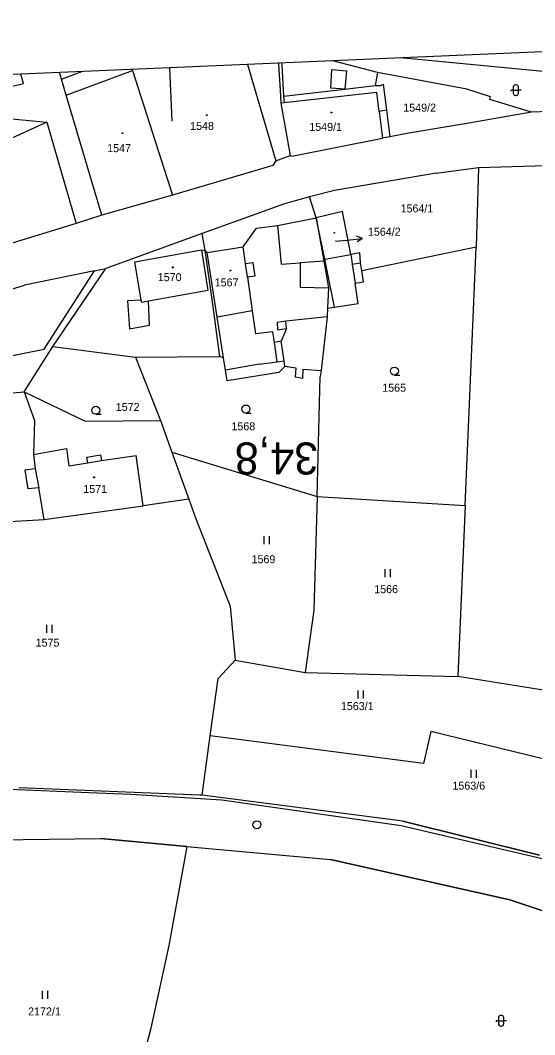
# Model space of a CAD drawing. Extents: x -806456 to -805395, y -1150847 to -1150506.
# Drawn here: x -805645 to -805548.5, y -1150696.2 to -1150506.1 of the extents above; entities that cross this region are included whole.
import ezdxf

# ---------------------------------------------------------------- set-up
doc = ezdxf.new("R2010")
doc.units = 0
for name, color, linetype in [('Default', 7, 'Continuous'), ('formát', 7, 'Continuous'), ('kilometráž - vrstava 7', 7, 'Continuous'), ('kn_celek - Cisla parcel pomocna', 7, 'Continuous'), ('kn_celek - Cisla pozemkovych parcel', 7, 'Continuous'), ('kn_celek - Cisla stavebnich parcel', 7, 'Continuous'), ('kn_celek - Hranice parcel', 7, 'Continuous'), ('kn_celek - Vnitrni kresby', 7, 'Continuous'), ('kn_celek - Znacky budov', 7, 'Continuous'), ('kn_celek - Znacky kultur', 7, 'Continuous'), ('plochy - SZDC', 7, 'Continuous'), ('PSR_C2_2_trasa_Vimperk - Kabelová trasa', 7, 'Continuous')]:
    doc.layers.add(name, color=color, linetype=linetype)

# ---------------------------------------------------------------- blocks, each defined once
blk = doc.blocks.new('316')
at = {"layer": 'Default'}
for p, q in [((0.5, 20), (-0.5, 20)), ((-8.3, 10), (-10, 8.1)), ((-5, 10), (-8.3, 10)), ((-5, 15.5), (-5, 4.5)), ((-5, 10), (5, 10)), ((-0.5, 0), (0.5, 0)), ((5, 4.5), (5, 15.5)), ((10, 10), (5, 10))]:
    blk.add_line(p, q, dxfattribs=at)
for centre, start, end in [((-0.5, 15.5), 90, 180), ((0.5, 15.5), 0, 90), ((-0.5, 4.5), 180, 270), ((0.5, 4.5), 270, 0)]:
    blk.add_arc(centre, 4.5, start, end, dxfattribs=at)
blk = doc.blocks.new('304')
at = {"layer": 'Default'}
blk.add_line((-0.1, 0), (9.9, 0), dxfattribs=at)
blk.add_circle((-0.1, 7.5), 7.5, dxfattribs=at)
blk = doc.blocks.new('306')
at = {"layer": 'Default'}
for p, q in [((-5.2, 0), (-5.2, 15)), ((4.8, 0), (4.8, 15))]:
    blk.add_line(p, q, dxfattribs=at)
blk = doc.blocks.new('402')
at = {"layer": 'Default'}
for p, q in [((-0.8, 0.8), (0.7, 0.8)), ((-0.8, 0.8), (-0.8, -0.7)), ((0.7, 0.8), (0.7, -0.7)), ((0.7, -0.7), (-0.8, -0.7))]:
    blk.add_line(p, q, dxfattribs=at)
blk = doc.blocks.new('Z61')
at = {"layer": 'Default'}
for p, q in [((0, 0), (30, 0)), ((30, 0), (19.2, 5.3)), ((30, 0), (19.2, -5.3))]:
    blk.add_line(p, q, dxfattribs=at)

msp = doc.modelspace()

# ---------------------------------------------------------------- linework, layer by layer
at = {"layer": 'formát'}
for p, q in [((-805407.21, -1150506.06), (-805617.02, -1150514.97)), ((-805617.02, -1150514.97), (-805826.83, -1150523.88)), ((-805617.02, -1150514.97), (-805616.59, -1150524.96))]:
    msp.add_line(p, q, dxfattribs=at)
at = {"layer": 'kilometráž - vrstava 7'}
msp.add_circle((-805600.62, -1150656.85), 0.75, dxfattribs=at)
at = {"layer": 'kn_celek - Cisla parcel pomocna'}
msp.add_line((-805585.87, -1150547.48), (-805583.79, -1150547.26), dxfattribs=at)
at = {"layer": 'kn_celek - Hranice parcel'}
for p, q in [((-805545.02, -1150515.82), (-805573.69, -1150513.13)), ((-805596.63, -1150514.1), (-805596.55, -1150514.37)), ((-805596.57, -1150514.1), (-805596.55, -1150514.37)), ((-805596.55, -1150514.37), (-805596.25, -1150519.18)), ((-805577.98, -1150515.83), (-805586.36, -1150513.67)), ((-805623.92, -1150515.45), (-805623.97, -1150515.26)), ((-805623.92, -1150515.45), (-805616.46, -1150538.83)), ((-805577.98, -1150515.83), (-805578.46, -1150518.31)), ((-805561.26, -1150518.96), (-805577.98, -1150515.83)), ((-805578.46, -1150518.31), (-805577.47, -1150518.27)), ((-805577.47, -1150518.27), (-805576.96, -1150518.06)), ((-805576.96, -1150518.06), (-805576.3, -1150522.94)), ((-805556.85, -1150520.42), (-805561.26, -1150518.96)), ((-805596.25, -1150519.18), (-805596.13, -1150521.6)), ((-805556.98, -1150520.91), (-805556.85, -1150520.42)), ((-805596.13, -1150521.6), (-805594.41, -1150531.4)), ((-805549.13, -1150523.27), (-805556.98, -1150520.91)), ((-805511.56, -1150521.75), (-805549.13, -1150523.27)), ((-805659.38, -1150523.36), (-805639.97, -1150525.18)), ((-805576.3, -1150522.94), (-805575.71, -1150527.92)), ((-805549.13, -1150523.27), (-805560.9, -1150525.36)), ((-805639.97, -1150525.18), (-805634.52, -1150544.15)), ((-805560.9, -1150525.36), (-805572.16, -1150527.23)), ((-805594.09, -1150531.56), (-805577.06, -1150528.18)), ((-805575.71, -1150527.92), (-805577.06, -1150528.18)), ((-805572.16, -1150527.23), (-805575.71, -1150527.92)), ((-805597.08, -1150532.42), (-805594.41, -1150531.4)), ((-805594.41, -1150531.4), (-805594.09, -1150531.56)), ((-805597.62, -1150533.3), (-805616.46, -1150538.83)), ((-805597.08, -1150532.42), (-805597.62, -1150533.3)), ((-805567, -1150534.69), (-805559.08, -1150533.65)), ((-805559.08, -1150533.65), (-805559.52, -1150548.6)), ((-805559.08, -1150533.65), (-805552.74, -1150533.48)), ((-805552.74, -1150533.48), (-805531.55, -1150532.9)), ((-805567, -1150534.69), (-805586.09, -1150537.99)), ((-805586.09, -1150537.99), (-805590.75, -1150539.15)), ((-805616.46, -1150538.83), (-805629.68, -1150542.61)), ((-805590.75, -1150539.15), (-805595.46, -1150540.47)), ((-805589.49, -1150543.12), (-805590.75, -1150539.15)), ((-805595.46, -1150540.47), (-805610.86, -1150546.01)), ((-805629.68, -1150542.61), (-805634.52, -1150544.15)), ((-805584.56, -1150541.93), (-805589.49, -1150543.12)), ((-805589.49, -1150543.12), (-805588.08, -1150551.24)), ((-805583.02, -1150549.97), (-805584.56, -1150541.93)), ((-805634.52, -1150544.15), (-805647.9, -1150548.27)), ((-805610.86, -1150546.01), (-805628.96, -1150552.57)), ((-805610.34, -1150549.2), (-805610.86, -1150546.01)), ((-805608.95, -1150558.85), (-805610.34, -1150549.2)), ((-805559.52, -1150548.6), (-805580.96, -1150553)), ((-805561.59, -1150597.03), (-805559.52, -1150548.6)), ((-805588.08, -1150551.24), (-805587.21, -1150556.23)), ((-805581.35, -1150549.67), (-805583.02, -1150549.97)), ((-805581.2, -1150551.5), (-805581.35, -1150549.67)), ((-805631.08, -1150553.04), (-805644.16, -1150555.7)), ((-805640.5, -1150567.71), (-805631.08, -1150553.04)), ((-805638.87, -1150567.2), (-805628.96, -1150552.57)), ((-805631.08, -1150553.04), (-805628.96, -1150552.57)), ((-805580.96, -1150553), (-805581.2, -1150551.5)), ((-805580.65, -1150555.07), (-805580.96, -1150553)), ((-805582.2, -1150555.31), (-805580.65, -1150555.07)), ((-805683.25, -1150567.84), (-805644.16, -1150555.7)), ((-805587.21, -1150556.23), (-805587.39, -1150560.01)), ((-805581.62, -1150559.15), (-805582.2, -1150555.31)), ((-805607.59, -1150569.08), (-805608.95, -1150558.85)), ((-805587.39, -1150560.01), (-805587.46, -1150561.66)), ((-805587.39, -1150560.01), (-805586.06, -1150559.81)), ((-805586.06, -1150559.81), (-805581.62, -1150559.15)), ((-805587.46, -1150561.66), (-805588.6, -1150571.69)), ((-805657.32, -1150571.01), (-805640.5, -1150567.71)), ((-805644.23, -1150575.69), (-805638.87, -1150567.2)), ((-805638.87, -1150567.2), (-805623.37, -1150569.23)), ((-805623.37, -1150569.23), (-805607.59, -1150569.08)), ((-805623.37, -1150569.23), (-805618.69, -1150581.09)), ((-805606.9, -1150569.31), (-805607.59, -1150569.08)), ((-805606.51, -1150571.62), (-805606.9, -1150569.31)), ((-805606.2, -1150573.64), (-805606.51, -1150571.62)), ((-805596.52, -1150572.06), (-805606.2, -1150573.64)), ((-805595.38, -1150570.95), (-805596.52, -1150572.06)), ((-805593.25, -1150571.25), (-805595.38, -1150570.95)), ((-805593.39, -1150572.95), (-805593.25, -1150571.25)), ((-805591.98, -1150571.46), (-805592.07, -1150573.19)), ((-805591.98, -1150571.46), (-805588.6, -1150571.69)), ((-805588.6, -1150571.69), (-805588.73, -1150572.86)), ((-805592.07, -1150573.19), (-805593.39, -1150572.95)), ((-805589.35, -1150595.34), (-805588.73, -1150572.86)), ((-805687.22, -1150579.45), (-805644.23, -1150575.69)), ((-805644.23, -1150575.69), (-805642.33, -1150581.09)), ((-805644.23, -1150575.69), (-805632.79, -1150581.21)), ((-805642.33, -1150581.09), (-805642.49, -1150587.43)), ((-805632.79, -1150581.21), (-805618.69, -1150581.09)), ((-805618.69, -1150581.09), (-805616.57, -1150587)), ((-805642.49, -1150587.43), (-805642.17, -1150590.12)), ((-805616.57, -1150587), (-805589.35, -1150595.34)), ((-805616.57, -1150587), (-805613.4, -1150595.85)), ((-805642.17, -1150590.12), (-805644.14, -1150590.41)), ((-805644.14, -1150590.41), (-805643.57, -1150593.9)), ((-805641.47, -1150593.73), (-805643.57, -1150593.9)), ((-805640.51, -1150599.62), (-805641.47, -1150593.73)), ((-805613.4, -1150595.85), (-805621.95, -1150597.06)), ((-805613.4, -1150595.85), (-805612.11, -1150599.32)), ((-805589.35, -1150595.34), (-805589.93, -1150616.61)), ((-805589.35, -1150595.34), (-805561.59, -1150597.03)), ((-805640.51, -1150599.62), (-805621.95, -1150597.06)), ((-805561.59, -1150597.03), (-805562.96, -1150629.07)), ((-805680.36, -1150601.92), (-805640.51, -1150599.62)), ((-805612.11, -1150599.32), (-805605.63, -1150615.87)), ((-805605.63, -1150615.87), (-805604.67, -1150626.03)), ((-805589.93, -1150616.61), (-805591.55, -1150628.29)), ((-805604.67, -1150626.03), (-805607.89, -1150629.47)), ((-805604.67, -1150626.03), (-805591.55, -1150628.29)), ((-805591.55, -1150628.29), (-805562.96, -1150629.07)), ((-805541.61, -1150632.52), (-805562.96, -1150629.07)), ((-805609.35, -1150640.16), (-805607.89, -1150629.47)), ((-805610.86, -1150651.29), (-805609.35, -1150640.16)), ((-805569.41, -1150645.37), (-805609.35, -1150640.16)), ((-805568.04, -1150639.35), (-805569.41, -1150645.37)), ((-805542.66, -1150645.56), (-805568.04, -1150639.35)), ((-805611.34, -1150651.29), (-805645.21, -1150649.93)), ((-805610.86, -1150651.29), (-805611.34, -1150651.29)), ((-805573.24, -1150656.2), (-805610.86, -1150651.29)), ((-805573.24, -1150656.2), (-805547.66, -1150662.54)), ((-805660.75, -1150659.79), (-805629.87, -1150659.45)), ((-805613.77, -1150660.92), (-805629.87, -1150659.45)), ((-805613.77, -1150660.92), (-805614.34, -1150664.04)), ((-805613.77, -1150660.92), (-805586.79, -1150663.39)), ((-805553.22, -1150670.95), (-805586.79, -1150663.39)), ((-805614.34, -1150664.04), (-805617.15, -1150679.49)), ((-805525.6, -1150680.1), (-805553.22, -1150670.95)), ((-805617.15, -1150679.49), (-805620.5, -1150694.98)), ((-805620.5, -1150694.98), (-805625.71, -1150715.25))]:
    msp.add_line(p, q, dxfattribs=at)
at = {"layer": 'kn_celek - Vnitrni kresby'}
for p, q in [((-805602.39, -1150514.35), (-805597.08, -1150532.42)), ((-805596, -1150514.08), (-805595.96, -1150514.45)), ((-805595.96, -1150514.45), (-805595.61, -1150520.29)), ((-805644.38, -1150517.91), (-805644.86, -1150516.15)), ((-805637.24, -1150517.09), (-805637.61, -1150515.84)), ((-805637.24, -1150517.09), (-805633.45, -1150515.67)), ((-805636.35, -1150520.07), (-805623.92, -1150515.45)), ((-805586.78, -1150518.78), (-805586.57, -1150515.31)), ((-805586.57, -1150515.31), (-805583.83, -1150515.54)), ((-805583.83, -1150515.54), (-805584.13, -1150518.98)), ((-805653.92, -1150520.23), (-805644.38, -1150517.91)), ((-805636.35, -1150520.07), (-805637.24, -1150517.09)), ((-805584.13, -1150518.98), (-805586.78, -1150518.78)), ((-805584.13, -1150518.98), (-805578.46, -1150518.31)), ((-805629.68, -1150542.61), (-805636.35, -1150520.07)), ((-805595.61, -1150520.29), (-805584.13, -1150518.98)), ((-805595.61, -1150520.29), (-805595.53, -1150521.53)), ((-805578.16, -1150519.57), (-805595.53, -1150521.53)), ((-805577.7, -1150523.19), (-805578.16, -1150519.57)), ((-805595.53, -1150521.53), (-805596.13, -1150521.6)), ((-805576.3, -1150522.94), (-805577.7, -1150523.19)), ((-805577.7, -1150523.19), (-805577.06, -1150528.18)), ((-805639.97, -1150525.18), (-805648.16, -1150528.9)), ((-805596.77, -1150544.52), (-805589.49, -1150543.12)), ((-805587.9, -1150550.85), (-805589.49, -1150543.12)), ((-805603.17, -1150548.54), (-805600.71, -1150545.04)), ((-805600.71, -1150545.04), (-805596.77, -1150544.52)), ((-805596.77, -1150544.52), (-805596.06, -1150551.79)), ((-805623.52, -1150551.37), (-805611.02, -1150549.07)), ((-805611.02, -1150549.07), (-805610.34, -1150549.2)), ((-805611.02, -1150549.07), (-805609.84, -1150556.74)), ((-805610.34, -1150549.2), (-805609.91, -1150549.62)), ((-805609.91, -1150549.62), (-805603.17, -1150548.54)), ((-805602.73, -1150551.65), (-805603.17, -1150548.54)), ((-805608.04, -1150561.69), (-805609.91, -1150549.62)), ((-805588.08, -1150551.24), (-805592.53, -1150551.55)), ((-805587.9, -1150550.85), (-805583.02, -1150549.97)), ((-805586.06, -1150559.81), (-805587.9, -1150550.85)), ((-805583.02, -1150549.97), (-805582.9, -1150550.78)), ((-805582.9, -1150550.78), (-805582.75, -1150551.75)), ((-805622.32, -1150558.5), (-805623.52, -1150551.37)), ((-805602.73, -1150551.65), (-805601.36, -1150551.44)), ((-805602.37, -1150554.2), (-805602.73, -1150551.65)), ((-805601.36, -1150551.44), (-805601, -1150554.01)), ((-805596.06, -1150551.79), (-805592.53, -1150551.55)), ((-805592.53, -1150551.55), (-805592.48, -1150556.11)), ((-805582.75, -1150551.75), (-805581.2, -1150551.5)), ((-805582.75, -1150551.75), (-805582.2, -1150555.31)), ((-805601, -1150554.01), (-805602.37, -1150554.2)), ((-805602.37, -1150554.2), (-805601.48, -1150560.51)), ((-805609.84, -1150556.74), (-805620.94, -1150558.73)), ((-805592.48, -1150556.11), (-805587.21, -1150556.23)), ((-805622.32, -1150558.5), (-805624.89, -1150558.65)), ((-805624.89, -1150558.65), (-805624.52, -1150563.92)), ((-805622.21, -1150558.95), (-805622.32, -1150558.5)), ((-805620.94, -1150558.73), (-805622.21, -1150558.95)), ((-805620.75, -1150563.24), (-805620.94, -1150558.73)), ((-805601.48, -1150560.51), (-805608.04, -1150561.69)), ((-805601.48, -1150560.51), (-805600.87, -1150564.84)), ((-805606.9, -1150569.31), (-805608.04, -1150561.69)), ((-805595.21, -1150562.46), (-805596.84, -1150562.73)), ((-805587.46, -1150561.66), (-805595.21, -1150562.46)), ((-805595.07, -1150563.86), (-805595.21, -1150562.46)), ((-805624.52, -1150563.92), (-805620.75, -1150563.24)), ((-805597.63, -1150564.46), (-805600.87, -1150564.84)), ((-805597.34, -1150566.43), (-805597.63, -1150564.46)), ((-805596.84, -1150562.73), (-805596.75, -1150564.1)), ((-805596.75, -1150564.1), (-805595.07, -1150563.86)), ((-805595.07, -1150563.86), (-805596.06, -1150566.22)), ((-805596.06, -1150566.22), (-805597.34, -1150566.43)), ((-805596.81, -1150570.08), (-805597.34, -1150566.43)), ((-805595.51, -1150569.91), (-805596.06, -1150566.22)), ((-805600.17, -1150570.51), (-805596.81, -1150570.08)), ((-805596.81, -1150570.08), (-805595.51, -1150569.91)), ((-805595.38, -1150570.95), (-805595.51, -1150569.91)), ((-805600.17, -1150570.51), (-805606.51, -1150571.62)), ((-805642.49, -1150587.43), (-805636.3, -1150586.33)), ((-805636.3, -1150586.33), (-805635.85, -1150589.55)), ((-805635.85, -1150589.55), (-805632.32, -1150589.01)), ((-805632.48, -1150587.94), (-805629.9, -1150587.54)), ((-805632.32, -1150589.01), (-805632.48, -1150587.94)), ((-805632.32, -1150589.01), (-805629.73, -1150588.61)), ((-805629.9, -1150587.54), (-805629.73, -1150588.61)), ((-805629.73, -1150588.61), (-805623.25, -1150587.64)), ((-805621.95, -1150597.06), (-805623.25, -1150587.64)), ((-805642.17, -1150590.12), (-805641.47, -1150593.73))]:
    msp.add_line(p, q, dxfattribs=at)
at = {"layer": 'plochy - SZDC'}
for p, q in [((-805611.34, -1150651.29), (-805645.21, -1150649.93)), ((-805610.86, -1150651.29), (-805611.34, -1150651.29)), ((-805573.24, -1150656.2), (-805610.86, -1150651.29)), ((-805547.66, -1150662.54), (-805573.24, -1150656.2)), ((-805660.75, -1150659.79), (-805629.87, -1150659.45)), ((-805629.87, -1150659.45), (-805613.77, -1150660.92)), ((-805613.77, -1150660.92), (-805586.79, -1150663.39)), ((-805586.79, -1150663.39), (-805553.22, -1150670.95)), ((-805553.22, -1150670.95), (-805525.6, -1150680.1))]:
    msp.add_line(p, q, dxfattribs=at)
at = {"layer": 'PSR_C2_2_trasa_Vimperk - Kabelová trasa'}
for points in [[(-805647.01, -1150650.18), (-805632.04, -1150650.81), (-805624.23, -1150651.13)], [(-805624.23, -1150651.13), (-805607.21, -1150652.21), (-805573.59, -1150656.97), (-805547.17, -1150663.21), (-805524.75, -1150670.52), (-805510.68, -1150674.8), (-805497.62, -1150678.19), (-805486.72, -1150680.63), (-805475.31, -1150683.18), (-805461.35, -1150684.65), (-805443.05, -1150686.29), (-805422.27, -1150685.42)]]:
    msp.add_lwpolyline(points, dxfattribs=at)

# ---------------------------------------------------------------- block references
at = {"layer": 'kn_celek - Cisla parcel pomocna', "xscale": 0.10000000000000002, "yscale": 0.10000000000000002, "rotation": 5.979509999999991}
msp.add_blockref('Z61', (-805583.79, -1150547.26), dxfattribs=at)
at = {"layer": 'kn_celek - Znacky budov', "xscale": 0.1, "yscale": 0.10000000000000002}
for p in [(-805610.03, -1150523.87), (-805586.67, -1150523.37), (-805625.84, -1150527.24), (-805586.12, -1150545.9), (-805616.39, -1150552.38), (-805605.59, -1150552.96), (-805631.15, -1150591.73)]:
    msp.add_blockref('402', p, dxfattribs=at)
at = {"layer": 'kn_celek - Znacky kultur', "xscale": 0.1, "yscale": 0.10000000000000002}
for name, p in [('316', (-805552.08, -1150520.16)), ('304', (-805574.83, -1150572.56)), ('304', (-805630.81, -1150579.92)), ('304', (-805602.67, -1150579.68)), ('306', (-805598.75, -1150604.28)), ('306', (-805576.07, -1150610.43)), ('306', (-805639.49, -1150620.88)), ('306', (-805581.09, -1150633.17)), ('306', (-805559.91, -1150648.08)), ('306', (-805640.27, -1150689.48)), ('316', (-805554.85, -1150694.6))]:
    msp.add_blockref(name, p, dxfattribs=at)

# ---------------------------------------------------------------- texts
at = {"layer": 'kilometráž - vrstava 7'}
msp.add_text('34,8', height=6, rotation=180, dxfattribs=at).set_placement((-805589.15, -1150585.2))
at = {"layer": 'kn_celek - Cisla parcel pomocna'}
msp.add_text('1564/2', height=1.5, dxfattribs=at).set_placement((-805579.81, -1150546.45))
at = {"layer": 'kn_celek - Cisla pozemkovych parcel'}
for s, p in [('1549/2', (-805573.18, -1150523.19)), ('1564/1', (-805573.69, -1150542.08)), ('1565', (-805577.12, -1150575.69)), ('1572', (-805627.07, -1150579.3)), ('1568', (-805605.39, -1150582.92)), ('1569', (-805601.62, -1150607.83)), ('1566', (-805578.63, -1150613.45)), ('1575', (-805642.09, -1150623.48)), ('1563/1', (-805584.87, -1150635.37)), ('1563/6', (-805563.97, -1150650.28)), ('2172/1', (-805643.5, -1150692.6))]:
    msp.add_text(s, height=1.5, dxfattribs=at).set_placement(p)
at = {"layer": 'kn_celek - Cisla stavebnich parcel'}
for s, p in [('1548', (-805613.13, -1150526.62)), ('1549/1', (-805590.8, -1150526.79)), ('1547', (-805628.68, -1150530.78)), ('1570', (-805619.19, -1150554.96)), ('1567', (-805608.52, -1150555.95)), ('1571', (-805633.16, -1150594.67))]:
    msp.add_text(s, height=1.5, dxfattribs=at).set_placement(p)
msp.add_text('1564/2', height=0.1, rotation=279, dxfattribs=at).set_placement((-805585.96, -1150547.22))

doc.saveas('drawing.dxf')
